// Mitsubishi GX Works2 project: jk3u从站站号1   PLC: FX3U/FX3UC

PROGRAM MAIN
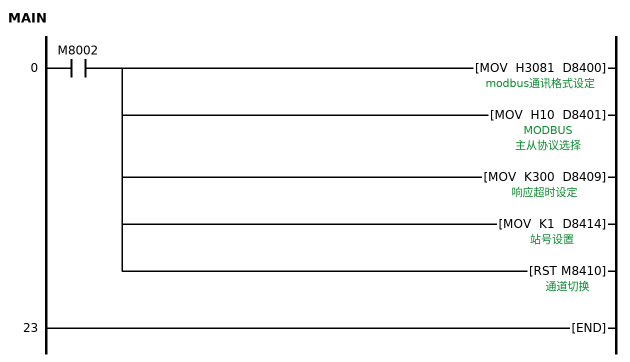
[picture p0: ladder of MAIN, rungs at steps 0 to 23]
0     LD      M8002
      MOV     H3081 D8400  ; modbus通讯格式设定
      MOV     H10 D8401  ; MODBUS 主从协议选择
      MOV     K300 D8409  ; 响应超时设定
      MOV     K1 D8414  ; 站号设置
      RST     M8410  ; 通道切换
23    END
END_PROGRAM
